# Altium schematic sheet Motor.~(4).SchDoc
size A4
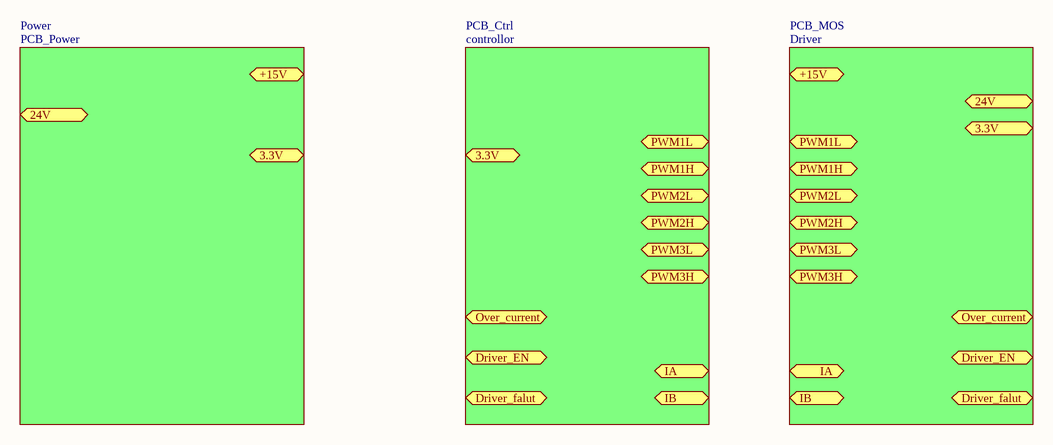
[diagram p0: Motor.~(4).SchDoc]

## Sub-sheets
PCB_Ctrl = controllor: no entries
PCB_MOS = Driver: no entries
PCB_Power = Power: no entries

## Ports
3.3V, 24V, +15V, Driver_EN, Driver_falut, IA, IB, Over_current, PWM1H, PWM1L, PWM2H, PWM2L, PWM3H, PWM3L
